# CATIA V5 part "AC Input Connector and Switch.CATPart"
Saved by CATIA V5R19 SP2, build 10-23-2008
Part number: AC Input Connector and Switch
Revision: ANY
Definition: UNKNOWN
Nomenclature: AC Input Connector and Switch
Source: Unknown
Bounding box of the stored display mesh (mm): x -24.731 to 24.731, y -27 to 27, z -32.1 to 8.2
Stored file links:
  Z:\fausse table rondelle-20220905T211342Z-001\fausse table rondelle\AC Input Connector and Switch.CATPart
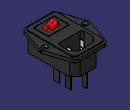
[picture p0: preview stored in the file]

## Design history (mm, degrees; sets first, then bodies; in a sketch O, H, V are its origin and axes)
AxisSystem1: origin (0, 0, 0), X (1, 0, 0), Y (0, 1, 0), Z (0, 0, 1)
Body1 "Extrude-Thin3" (main body)
  Solid1: solid without history
Body2 "Split Line1"
  Solid2: solid without history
